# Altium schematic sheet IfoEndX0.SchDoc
size C; Engineer: Daniel Sigg; DocumentNumber: 4; SheetNumber: 23; SheetTotal: 33
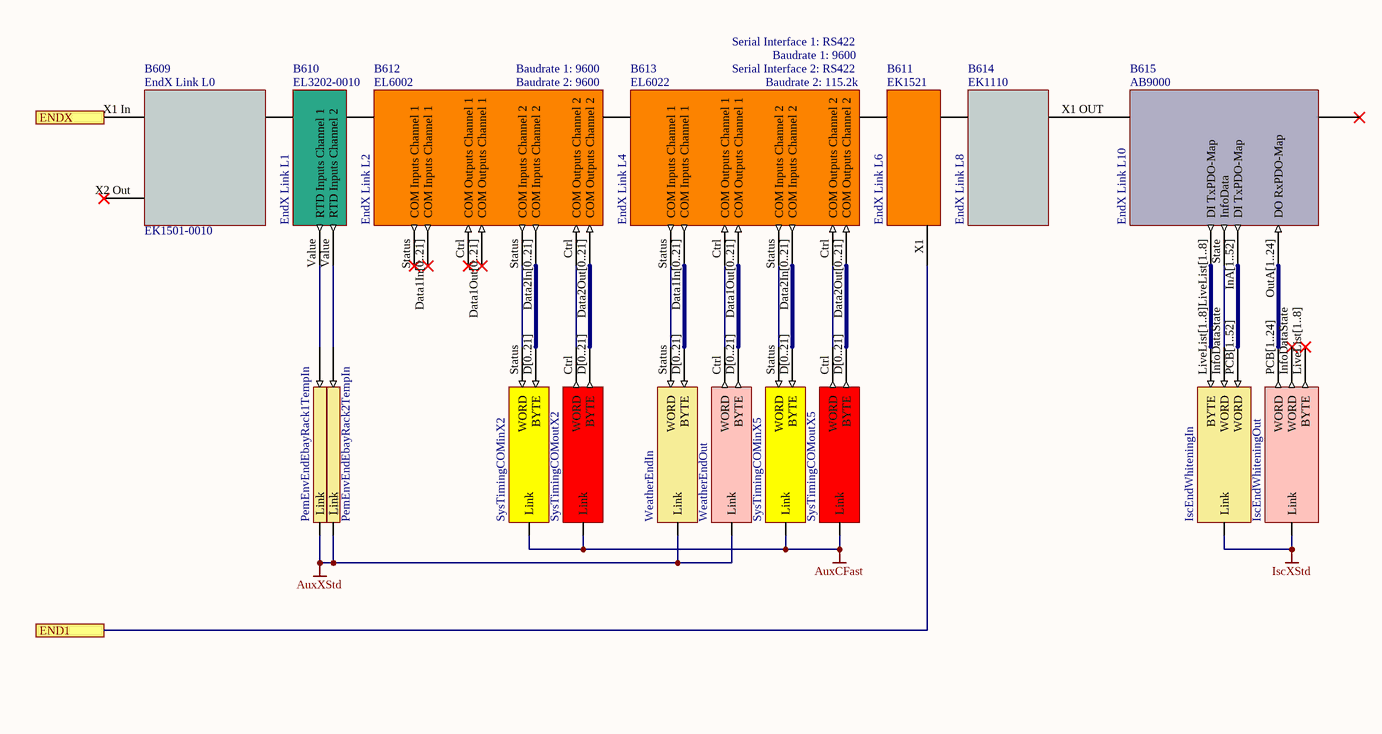
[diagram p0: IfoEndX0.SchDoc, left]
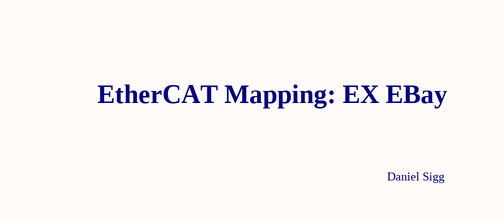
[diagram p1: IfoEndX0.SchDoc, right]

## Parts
B609  EndX Link L0  Part Number: EK1501-0010  (mechanical)
B610  EndX Link L1  Part Number: EL3202-0010  (mechanical)
B611  EndX Link L6  Part Number: EK1521  (mechanical)
B612  EndX Link L2  Part Number: EL6002  Baudrate 1: 9600  (mechanical)
B613  EndX Link L4  Part Number: EL6022  Baudrate 1: 9600  Baudrate 2: 115.2k  Serial Interface 1: RS422  (mechanical)
B614  EndX Link L8  Part Number: EK1110  (mechanical)
B615  EndX Link L10  Part Number: AB9000  (mechanical)
V526  PemEnvEndEbayRack1TempIn  (no BOM)
V527  PemEnvEndEbayRack2TempIn  (no BOM)
V528  IscEndWhiteningIn  (no BOM)
V529  IscEndWhiteningOut  (no BOM)
V530  SysTimingCOMinX2  (no BOM)
V531  SysTimingCOMoutX2  (no BOM)
V533  SysTimingCOMinX5  (no BOM)
V534  SysTimingCOMoutX5  (no BOM)
V845  WeatherEndIn  (no BOM)
V846  WeatherEndOut  (no BOM)

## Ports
END1, ENDX

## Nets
AuxCFast: V530.?1(Link) V531.?1(Link) V533.?1(Link) V534.?1(Link)
AuxXStd: V526.?2(Link) V527.?2(Link) V845.?1(Link) V846.?1(Link)
IscXStd: V528.?1(Link) V529.?1(Link)
END1: B611.X1(D) ; port END1
ENDX: B609.X1_In(A) ; port ENDX
NetB609_Ebus: B609.Ebus(B) B610.Ebus(A)
NetB610_Ebus: B610.Ebus(B) B612.Ebus(A)
NetB610_Value: B610.Value(RTD_Inputs_Channel_1) V526.?1
NetB610_Value: B610.Value(RTD_Inputs_Channel_2) V527.?1  [a separate net that carries the same name]
NetB611_Ebus: B611.Ebus(A) B613.Ebus(B)
NetB611_Ebus: B611.Ebus(C) B614.Ebus(A)  [a separate net that carries the same name]
NetB612_Ctrl: B612.Ctrl(COM_Outputs_Channel_1) V531.Ctrl(WORD)
NetB612_Data2In[0..21]: B612.Data2In[0..21](COM_Inputs_Channel_2) V530.D[0..21](BYTE)
NetB612_Data2Out[0..21]: B612.Data2Out[0..21](COM_Outputs_Channel_2) V531.D[0..21](BYTE)
NetB612_Ebus: B612.Ebus(B) B613.Ebus(A)
NetB612_Status: B612.Status(COM_Inputs_Channel_1) V530.Status(WORD)
NetB613_Ctrl: B613.Ctrl(COM_Outputs_Channel_1) V846.Ctrl(WORD)
NetB613_Ctrl: B613.Ctrl(COM_Outputs_Channel_2) V534.Ctrl(WORD)  [a separate net that carries the same name]
NetB613_Data1In[0..21]: B613.Data1In[0..21](COM_Inputs_Channel_1) V845.D[0..21](BYTE)
NetB613_Data1Out[0..21]: B613.Data1Out[0..21](COM_Outputs_Channel_1) V846.D[0..21](BYTE)
NetB613_Data2In[0..21]: B613.Data2In[0..21](COM_Inputs_Channel_2) V533.D[0..21](BYTE)
NetB613_Data2Out[0..21]: B613.Data2Out[0..21](COM_Outputs_Channel_2) V534.D[0..21](BYTE)
NetB613_Status: B613.Status(COM_Inputs_Channel_1) V845.Status(WORD)
NetB613_Status: B613.Status(COM_Inputs_Channel_2) V533.Status(WORD)  [a separate net that carries the same name]
NetB614_X1 OUT: B614.X1_OUT(B) B615.?2(A)
NetB615_InA[1..52]: B615.InA[1..52](DI_TxPDO-Map) V528.PCB[1..52](WORD)
NetB615_LiveList[1..8]: B615.LiveList[1..8](DI_TxPDO-Map) V528.LiveList[1..8](BYTE)
NetB615_OutA[1..24]: B615.OutA[1..24](DO_RxPDO-Map) V529.PCB[1..24](WORD)
NetB615_State: B615.State(InfoData) V528.InfoDataState(WORD)

Not connected (* = marked no-connect by the designer): B609 X2 Out(C)*; B612 Data1In[0..21](COM_Inputs_Channel_1)* Data1Out[0..21](COM_Outputs_Channel_1)*; B615 ?1(B)*; V529 InfoDataState(WORD)* LiveList[1..8](BYTE)*

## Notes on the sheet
- EtherCAT Mapping: EX EBay
- Daniel Sigg

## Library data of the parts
B609 = CouplerEK1501: Fiber Coupler; Rail: Left; BoxNextB: UNLNFJLN; BoxPrev: CLSUUFOZ; PortPrevFull: 1001/B; PortPrevShort: B 'X1'; Fullname: TIID^End X (EtherCAT)^EndX Link L0 (EK1501-0010); BoxPorts: Junction; BoxAddr: 1002; Disabled: False
B610 = TerminalEL3202-0010: EtherCAT Terminal EL3202-0010 2-chn Temperature Input; Rail: Left; BoxNextB: FGQAFBHR; BoxPrev: PMEMEWCT; PortPrevFull: 1002/B; PortPrevShort: B; Fullname: TIID^End X (EtherCAT)^EndX Link L0 (EK1501-0010)^EndX Link L1 (EL3202-0010); BoxAddr: 1003; Disabled: False
B611 = TerminalEK1521: EtherCAT Terminal Fiber; Rail: Left; BoxNextC: IBXWRMDF; BoxNextD: QEYXEFKI; BoxPrev: BNXINGGL; PortPrevFull: 1005/B; PortPrevShort: B; Fullname: TIID^End X (EtherCAT)^EndX Link L0 (EK1501-0010)^EndX Link L6 (EK1521); BoxPorts: Junction; BoxAddr: 1006; Disabled: False
B612 = TerminalEL6002: EtherCAT Terminal EL6002 Dual RS232; Rail: Left; BoxNextB: BNXINGGL; BoxPrev: UNLNFJLN; PortPrevFull: 1003/B; PortPrevShort: B; Fullname: TIID^End X (EtherCAT)^EndX Link L0 (EK1501-0010)^EndX Link L2 (EL6002); BoxAddr: 1004; BoxSubType: 9101; Disabled: False
B613 = TerminalEL6022: EtherCAT Terminal EL6022 Dual RS422; Rail: Left; BoxNextB: QCEWWLIP; BoxPrev: FGQAFBHR; PortPrevFull: 1004/B; PortPrevShort: B; Fullname: TIID^End X (EtherCAT)^EndX Link L0 (EK1501-0010)^EndX Link L4 (EL6022); BoxAddr: 1005; BoxSubType: 9103; Disabled: False
B614 = CouplerEK1110: EtherCAT Coupler Extension; BoxType: Terminal; Rail: Left; BoxNextB: PSHPKMCT; BoxPrev: QCEWWLIP; PortPrevFull: 1006/C; PortPrevShort: C; Fullname: TIID^End X (EtherCAT)^EndX Link L0 (EK1501-0010)^EndX Link L8 (EK1110); BoxAddr: 1126; Disabled: False
B615 = Anybus X-gateway 1xBIO: EtherCAT Modbus gateway for 1xBIO; Part Revision: V0000001b_P0000001b_R0001000d; BoxType: Box; BoxPrev: IBXWRMDF; PortPrevFull: 1126/B; PortPrevShort: B 'X1 OUT'; Fullname: TIID^End X (EtherCAT)^EndX Link L10 (AB9000); BoxAddr: 1127; PDO Inputs: 0x1A01; PDO Outputs: 0x1601; Disabled: False
V526 V527 = VariableInINT: INT; PLC: H1AuxEndX; Task: AuxEStd; Instance: H1AuxEndX Instance
V528 = ISCWhitening_IscWhiteningInStruct: IscWhiteningInStruct; BoxType: Variable; Instance: H1IscEndX Instance; PLC: H1IscEndX; Task: IscEStd
V529 = ISCWhitening_IscWhiteningOutStruct: IscWhiteningOutStruct; BoxType: Variable; Instance: H1IscEndX Instance; PLC: H1IscEndX; Task: IscEStd
V530 V533 = Serial_EL6inData22Bfast: EL6inData22B; PLC: H1AuxCorner; Task: AuxCFast; BoxType: Variable; Instance: H1AuxCorner Instance
V531 V534 = Serial_EL6outData22Bfast: EL6outData22B; PLC: H1AuxCorner; Task: AuxCFast; BoxType: Variable; Instance: H1AuxCorner Instance
V845 = Serial_EL6inData22B: EL6inData22B; PLC: H1AuxEndX; Task: AuxEStd; BoxType: Variable; Instance: H1AuxEndX Instance
V846 = Serial_EL6outData22B: EL6outData22B; PLC: H1AuxEndX; Task: AuxEStd; BoxType: Variable; Instance: H1AuxEndX Instance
